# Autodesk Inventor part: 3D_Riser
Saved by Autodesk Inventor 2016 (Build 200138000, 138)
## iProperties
Created: 2016-01
Part Number: 3D_Riser
Material: Generic
Document SubType Name: Modeling
Designer: John
Density: 1 g/cm^3
Appearance: Default
Author: John
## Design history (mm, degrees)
feature "SOLID1"
body "Solid1"
